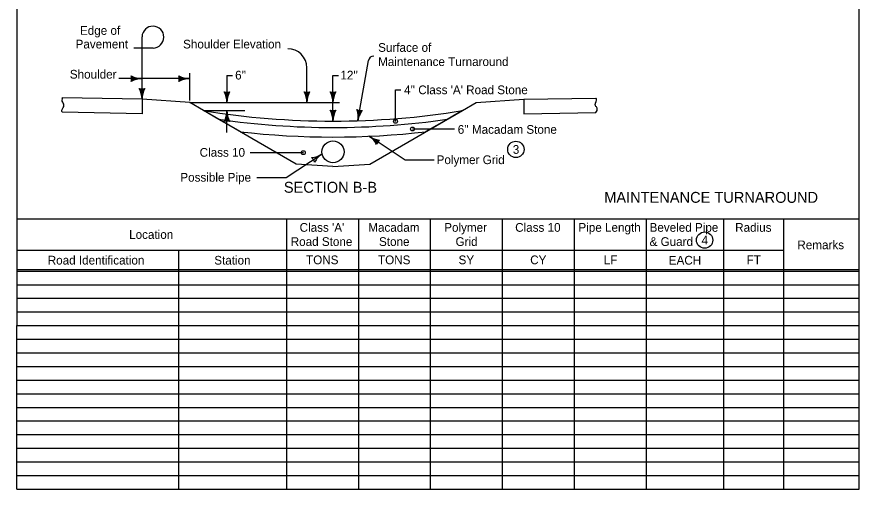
# Model space of a CAD drawing. Extents: x -772 to 772, y -957 to 657.
# Drawn here: x -772 to 772, y -957 to -91 of the extents above; entities that cross this region are included whole.
import ezdxf

# ---------------------------------------------------------------- set-up
doc = ezdxf.new("R2010")
doc.units = 0
for name, color, linetype in [('dsnCellElements', 7, 'Continuous'), ('dsnStdDetailExtension', 7, 'Continuous'), ('dsnStdNote', 7, 'Continuous'), ('Level 1', 7, 'Continuous'), ('Level 2', 7, 'Continuous'), ('Level 3', 7, 'Continuous'), ('Level 4', 7, 'Continuous')]:
    doc.layers.add(name, color=color, linetype=linetype)

msp = doc.modelspace()

# ---------------------------------------------------------------- linework, layer by layer
at = {"layer": 'dsnCellElements'}
msp.add_lwpolyline([(-772.5, 657.5), (-772.5, -657.5), (772.5, -657.5), (772.5, 657.5), (-772.5, 657.5)], dxfattribs=at)
for centre in [(-77.9, -283), (-46.8, -297), (-247, -340.4)]:
    msp.add_circle(centre, 3.54, dxfattribs=at)
at = {"layer": 'dsnStdDetailExtension'}
for p, q in [((-772.5, -957.5), (-772.5, -657.5)), ((-475.5, -957.5), (-475.5, -657.5)), ((-277.5, -957.5), (-277.5, -657.5)), ((-145.5, -957.5), (-145.5, -657.5)), ((-13.5, -957.5), (-13.5, -657.5)), ((118.5, -957.5), (118.5, -657.5)), ((250.5, -957.5), (250.5, -657.5)), ((382.5, -957.5), (382.5, -657.5)), ((524.5, -957.5), (524.5, -657.5)), ((634.5, -957.5), (634.5, -657.5)), ((772.5, -957.5), (772.5, -657.5)), ((-772.5, -682.5), (772.5, -682.5)), ((-772.5, -707.5), (772.5, -707.5)), ((-772.5, -732.5), (772.5, -732.5)), ((-772.5, -757.5), (772.5, -757.5)), ((-772.5, -782.5), (772.5, -782.5)), ((-772.5, -807.5), (772.5, -807.5)), ((-772.5, -832.5), (772.5, -832.5)), ((-772.5, -857.5), (772.5, -857.5)), ((-772.5, -882.5), (772.5, -882.5)), ((-772.5, -907.5), (772.5, -907.5)), ((-772.5, -932.5), (772.5, -932.5)), ((-772.5, -957.5), (772.5, -957.5))]:
    msp.add_line(p, q, dxfattribs=at)
at = {"layer": 'dsnStdNote'}
for centre in [(142.8, -334.5), (489.1, -500.8)]:
    msp.add_circle(centre, 15, dxfattribs=at)
at = {"layer": 'Level 1'}
for p, q in [((-772.5, -461.5), (772.5, -461.5)), ((-277.5, -657.5), (-277.5, -461.5)), ((-145.5, -657.5), (-145.5, -461.5)), ((-13.5, -657.5), (-13.5, -461.5)), ((118.5, -657.5), (118.5, -461.5)), ((250.5, -657.5), (250.5, -461.5)), ((382.5, -657.5), (382.5, -461.5)), ((524.5, -657.5), (524.5, -461.5)), ((634.5, -657.5), (634.5, -461.5)), ((-772.5, -519.5), (634.5, -519.5)), ((-475.5, -657.5), (-475.5, -519.5)), ((-772.5, -554.5), (772.5, -554.5)), ((-772.5, -557.5), (772.5, -557.5))]:
    msp.add_line(p, q, dxfattribs=at)
at = {"layer": 'Level 2'}
for p, q in [((-542.9, -185.7), (-542.9, -127.9)), ((-522.7, -148.5), (-557.7, -148.5)), ((-240.5, -248.7), (-240.5, -184.8)), ((-147.2, -281.8), (-127.7, -171.4)), ((-542.9, -242.6), (-542.9, -185.7)), ((-455.2, -244.7), (-455.2, -194.7)), ((-387.2, -198.7), (-377.2, -198.7)), ((-387.2, -198.7), (-387.2, -248.7)), ((-192.6, -282.5), (-192.6, -198.7)), ((-192.6, -198.7), (-182.6, -198.7)), ((-455.2, -204.7), (-585.6, -204.6)), ((-542.9, -242.6), (-542.9, -223.3)), ((-240.5, -248.7), (-240.5, -229.5)), ((-77.9, -283), (-77.9, -225.3)), ((-77.9, -225.3), (-67.9, -225.3)), ((-542.9, -242.6), (-689.3, -240)), ((-688.7, -241.6), (-689.3, -240)), ((-455.2, -248.7), (-542.9, -242.6)), ((-542.9, -242.6), (-542.9, -268.9)), ((70.1, -248.7), (157.7, -242.6)), ((157.7, -242.6), (289.4, -240.3)), ((157.7, -242.6), (157.7, -268.9)), ((290, -240.9), (289.4, -240.3)), ((-429.9, -263.3), (-455.2, -248.7)), ((-455.2, -248.7), (-180.5, -248.7)), ((44.7, -263.3), (70.1, -248.7)), ((-689.4, -266.3), (-689.4, -266.4)), ((-542.9, -268.9), (-689.4, -266.4)), ((-429.9, -263.3), (-354.4, -263.3)), ((-402.3, -279.3), (-429.9, -263.3)), ((-260.4, -361.2), (-429.9, -263.3)), ((-363.1, -301.9), (-429.9, -263.3)), ((-387.2, -303.3), (-387.2, -263.3)), ((-124.8, -361.2), (44.7, -263.3)), ((-22.1, -301.9), (44.7, -263.3)), ((44.7, -263.3), (17.1, -279.3)), ((157.7, -268.9), (289.5, -266.6)), ((-363.1, -301.9), (-402.3, -279.3)), ((17.1, -279.3), (-22.1, -301.9)), ((-46.8, -297), (30, -297)), ((-344.4, -340.4), (-247, -340.4)), ((-192.6, -365.9), (-260.4, -361.2)), ((-192.6, -365.9), (-124.8, -361.2)), ((-772.5, -657.5), (217.5, -657.5))]:
    msp.add_line(p, q, dxfattribs=at)
for points in [[(-561.7, -201.1), (-561, -204.7), (-561.7, -208.3), (-557.4, -206.2), (-550.6, -204.7), (-557.9, -203), (-561.1, -201.6), (-560.3, -204.7), (-560.6, -207), (-557.8, -205.7), (-554, -204.7), (-558, -203.5), (-560.1, -202.8), (-559.8, -205.9), (-557, -204.7), (-559.2, -204), (-559.2, -205.1), (-558.2, -204.7)], [(-474.1, -201.1), (-473.4, -204.7), (-474.1, -208.3), (-469.8, -206.2), (-463, -204.7), (-470.3, -203), (-473.5, -201.6), (-472.7, -204.7), (-473, -207), (-470.2, -205.7), (-466.4, -204.7), (-470.4, -203.5), (-472.5, -202.8), (-472.1, -205.9), (-469.3, -204.7), (-471.5, -204), (-471.5, -205.1), (-470.5, -204.7)], [(-539.3, -223.7), (-542.9, -224.5), (-546.5, -223.7), (-544.4, -228), (-542.9, -234.8), (-541.2, -227.5), (-539.8, -224.3), (-542.9, -225.1), (-545.2, -224.8), (-543.9, -227.6), (-542.9, -231.4), (-541.7, -227.4), (-541, -225.3), (-544.1, -225.7), (-542.9, -228.5), (-542.2, -226.3), (-543.3, -226.3), (-542.9, -227.3)], [(-383.6, -229.9), (-387.2, -230.6), (-390.8, -229.8), (-388.8, -234.1), (-387.2, -241), (-385.5, -233.6), (-384.1, -230.5), (-387.2, -231.2), (-389.5, -230.9), (-388.2, -233.8), (-387.2, -237.6), (-386.1, -233.5), (-385.3, -231.4), (-388.4, -231.8), (-387.2, -234.6), (-386.5, -232.4), (-387.6, -232.4), (-387.3, -233.4)], [(-237, -229.9), (-240.6, -230.6), (-244.2, -229.8), (-242.1, -234.1), (-240.6, -241), (-238.9, -233.6), (-237.4, -230.5), (-240.6, -231.2), (-242.9, -230.9), (-241.5, -233.8), (-240.6, -237.6), (-239.4, -233.5), (-238.7, -231.4), (-241.7, -231.8), (-240.6, -234.6), (-239.9, -232.4), (-240.9, -232.4), (-240.6, -233.4)], [(-189, -229.9), (-192.6, -230.6), (-196.2, -229.8), (-194.1, -234.1), (-192.6, -241), (-190.9, -233.6), (-189.5, -230.5), (-192.6, -231.2), (-194.9, -230.9), (-193.6, -233.8), (-192.6, -237.6), (-191.4, -233.5), (-190.7, -231.4), (-193.8, -231.8), (-192.6, -234.6), (-191.9, -232.4), (-193, -232.4), (-192.6, -233.4)], [(-140.4, -263.9), (-144, -264), (-147.5, -262.6), (-146.2, -267.2), (-145.8, -274.2), (-142.9, -267.2), (-140.9, -264.4), (-144.2, -264.6), (-146.4, -263.9), (-145.5, -266.9), (-145.3, -270.8), (-143.4, -267.1), (-142.3, -265.1), (-145.4, -265), (-144.7, -267.9), (-143.7, -265.9), (-144.7, -265.7), (-144.6, -266.7)], [(-390.8, -282.2), (-387.2, -281.4), (-383.6, -282.2), (-385.7, -277.9), (-387.2, -271.1), (-388.9, -278.4), (-390.3, -281.6), (-387.2, -280.8), (-384.9, -281.1), (-386.2, -278.3), (-387.2, -274.5), (-388.4, -278.5), (-389.1, -280.6), (-386, -280.2), (-387.2, -277.4), (-387.9, -279.6), (-386.8, -279.6), (-387.2, -278.6)], [(-189, -263.7), (-192.6, -264.4), (-196.2, -263.6), (-194.1, -267.9), (-192.6, -274.7), (-190.9, -267.4), (-189.5, -264.3), (-192.6, -265), (-194.9, -264.7), (-193.6, -267.6), (-192.6, -271.4), (-191.4, -267.3), (-190.7, -265.2), (-193.8, -265.6), (-192.6, -268.4), (-191.9, -266.2), (-193, -266.2), (-192.6, -267.2)], [(-6.8, -354), (-60.3, -354), (-126.4, -310.3)], [(-112.8, -323.8), (-111.4, -320.4), (-108.8, -317.8), (-113.5, -317.1), (-120, -314.6), (-114.9, -320.1), (-113.1, -323.1), (-112, -320), (-110.4, -318.3), (-113.5, -317.8), (-117.2, -316.5), (-114.5, -319.7), (-113.2, -321.5), (-111.8, -318.7), (-114.8, -318.1), (-113.3, -319.9), (-112.7, -319.1), (-113.8, -318.8)], [(-332.1, -386.2), (-278.6, -386.2), (-212.4, -342.4)]]:
    msp.add_lwpolyline(points, dxfattribs=at)
for centre, radius, start, end in [((-522.9, -128.5), 20, 270.5217, 178.1606), ((-275.5, -184.8), 35, 0, 90), ((-117.9, -173.2), 10, 90, 170.0026), ((-578.5, -204.7), 16.4, 342.2666, 17.7333), ((-542.9, -162.2), 42.5, 241.9275, 270), ((-490.9, -204.7), 16.4, 342.2666, 17.7333), ((-455.2, -162.2), 42.5, 241.9275, 270), ((-542.9, -247.2), 42.5, 90, 118.0725), ((-455.2, -247.2), 42.5, 90, 118.0725), ((-542.9, -206.9), 16.4, 252.2666, 287.7333), ((-585.4, -242.6), 42.5, 0, 28.0725), ((-500.4, -242.6), 42.5, 151.9275, 180), ((-387.2, -213.1), 16.4, 252.2666, 287.7333), ((-429.7, -248.7), 42.5, 0, 28.0725), ((-344.7, -248.7), 42.5, 151.9275, 180), ((-240.5, -213.1), 16.4, 252.2666, 287.7333), ((-283, -248.7), 42.5, 0, 28.0725), ((-198, -248.7), 42.5, 151.9275, 180), ((-192.6, -213.1), 16.4, 252.2666, 287.7333), ((-235.1, -248.7), 42.5, 0, 28.0725), ((-150.1, -248.7), 42.5, 151.9275, 180), ((-192.6, -246.8), 16.4, 252.2666, 287.7333), ((-235.1, -282.5), 42.5, 0, 28.0725), ((-150.1, -282.5), 42.5, 151.9275, 180), ((-141, -246.7), 16.4, 242.2666, 277.7333), ((-189, -274.4), 42.5, 350, 18.0725), ((-192.6, 1197.2), 1479.7, 260.7715, 279.2285), ((-192.6, 1197.2), 1479.7, 260.7715, 279.2285), ((-429.7, -263.3), 42.5, 331.9275, 0), ((-344.7, -263.3), 42.5, 180, 208.0725), ((-105.3, -289.2), 42.5, 141.9275, 170), ((-192.6, 1185.5), 1479.7, 261.8522, 278.1478), ((-192.6, 1185.5), 1479.7, 261.8522, 278.1478), ((-192.6, 1185.5), 1479.7, 261.8522, 278.1478), ((-387.2, -299), 16.4, 72.2666, 107.7334), ((-192.6, 1167.9), 1479.7, 263.3842, 276.6158), ((-192.6, 1167.9), 1479.7, 263.3842, 276.6158), ((-102.7, -275.1), 42.5, 236, 264.0725), ((-150.2, -345.5), 42.5, 27.9275, 56), ((-96.9, -330.2), 16.4, 128.2666, 163.7334), ((-236.2, -307.2), 42.5, 275.9275, 304), ((-242, -362.4), 16.4, 16.2667, 51.7334), ((-188.7, -377.7), 42.5, 124, 152.0725)]:
    msp.add_arc(centre, radius, start, end, dxfattribs=at)
for points in [[(-689.4, -266.3), (-689.7, -262.4), (-686.1, -253.4), (-689.1, -246.1), (-688.7, -241.6)], [(289.5, -266.6), (291.7, -263.1), (291.9, -258.7), (289.1, -254.5), (288.5, -252.6), (290.5, -241.6), (290, -240.9)]]:
    msp.add_spline(points, degree=3, dxfattribs=at)
at = {"layer": 'Level 3'}
for p, q in [((-772.5, -582.5), (772.5, -582.5)), ((-772.5, -607.5), (772.5, -607.5)), ((-772.5, -632.5), (772.5, -632.5))]:
    msp.add_line(p, q, dxfattribs=at)
at = {"layer": 'Level 4'}
msp.add_circle((-192.6, -338.9), 20.2, dxfattribs=at)

# ---------------------------------------------------------------- texts
at = {"layer": 'Level 2'}
for s, p in [("Class 'A'", (-253.8, -485.5)), ('Macadam', (-127.9, -485.5)), ('Polymer', (11.4, -485.5)), ('Class 10', (141.6, -485.5)), ('Pipe Length', (257.6, -485.5)), ('Beveled Pipe', (388.1, -485.5)), ('Radius', (545.1, -485.5)), ('Location', (-566.5, -498.5)), ('Road Stone', (-270.1, -511.5)), ('Stone', (-108.2, -511.5)), ('Grid', (32.2, -511.5)), ('& Guard', (388.1, -511.5)), ('Remarks', (659.2, -517.5)), ('Road Identification', (-715.8, -545.6)), ('Station', (-410.4, -545.7)), ('TONS', (-242, -545)), ('TONS', (-110, -545)), ('SY', (37.7, -545)), ('CY', (169.1, -545)), ('LF', (304, -545)), ('EACH', (423.3, -545.7)), ('FT', (566.1, -545))]:
    msp.add_text(s, height=16, dxfattribs=at).set_placement(p)
at = {"layer": 'Level 3'}
for s, height, p in [('Edge of', 16, (-656.7, -124.3)), ('Pavement', 16, (-664.8, -149.3)), ('Shoulder Elevation', 16, (-467.6, -149.3)), ('Surface of ', 16, (-109.8, -155.5)), ('Maintenance Turnaround', 16, (-109.8, -181.5)), ('Shoulder', 16, (-675.3, -204.6)), ("6''", 16, (-372.1, -206.2)), ("12''", 16, (-179, -206.2)), ("4'' Class 'A' Road Stone", 16, (-62.2, -233.2)), ("6'' Macadam Stone", 16, (36.2, -305.8)), ('Class 10', 16, (-437.2, -347.9)), ('3', 16, (137.2, -342.5)), ('Polymer Grid', 16, (-2.5, -361.4)), ('Possible Pipe', 16, (-472.6, -393.6)), ('SECTION B-B', 20, (-282.7, -413.9)), ('MAINTENANCE TURNAROUND', 20, (304.9, -432.4)), ('4', 16, (483.4, -508.8))]:
    msp.add_text(s, height=height, dxfattribs=at).set_placement(p)

doc.saveas('drawing.dxf')
